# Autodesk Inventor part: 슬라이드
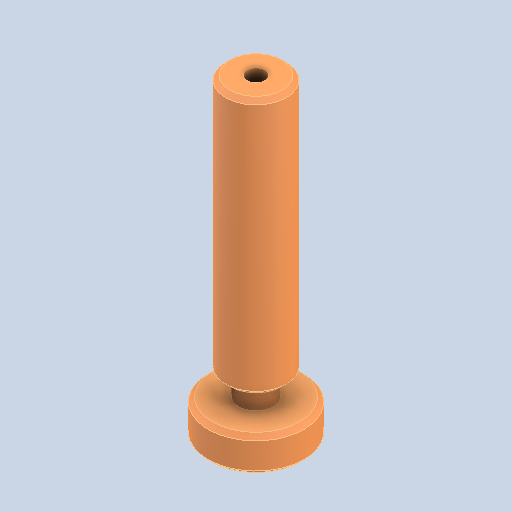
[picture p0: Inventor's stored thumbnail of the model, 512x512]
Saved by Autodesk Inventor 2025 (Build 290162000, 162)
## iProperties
Created: 2024-07
Part Number: 슬라이드
Material: 강철, 연강
Document SubType Name: Modeling
Designer: myung
Density: 7.86 g/cm^3
Appearance: 기본값
Author: jhkim
Sending System: Autodesk Inventor 2025
Preprocessor: ST-DEVELOPER v20
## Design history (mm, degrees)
feature "솔리드1"
node "솔리드2"
